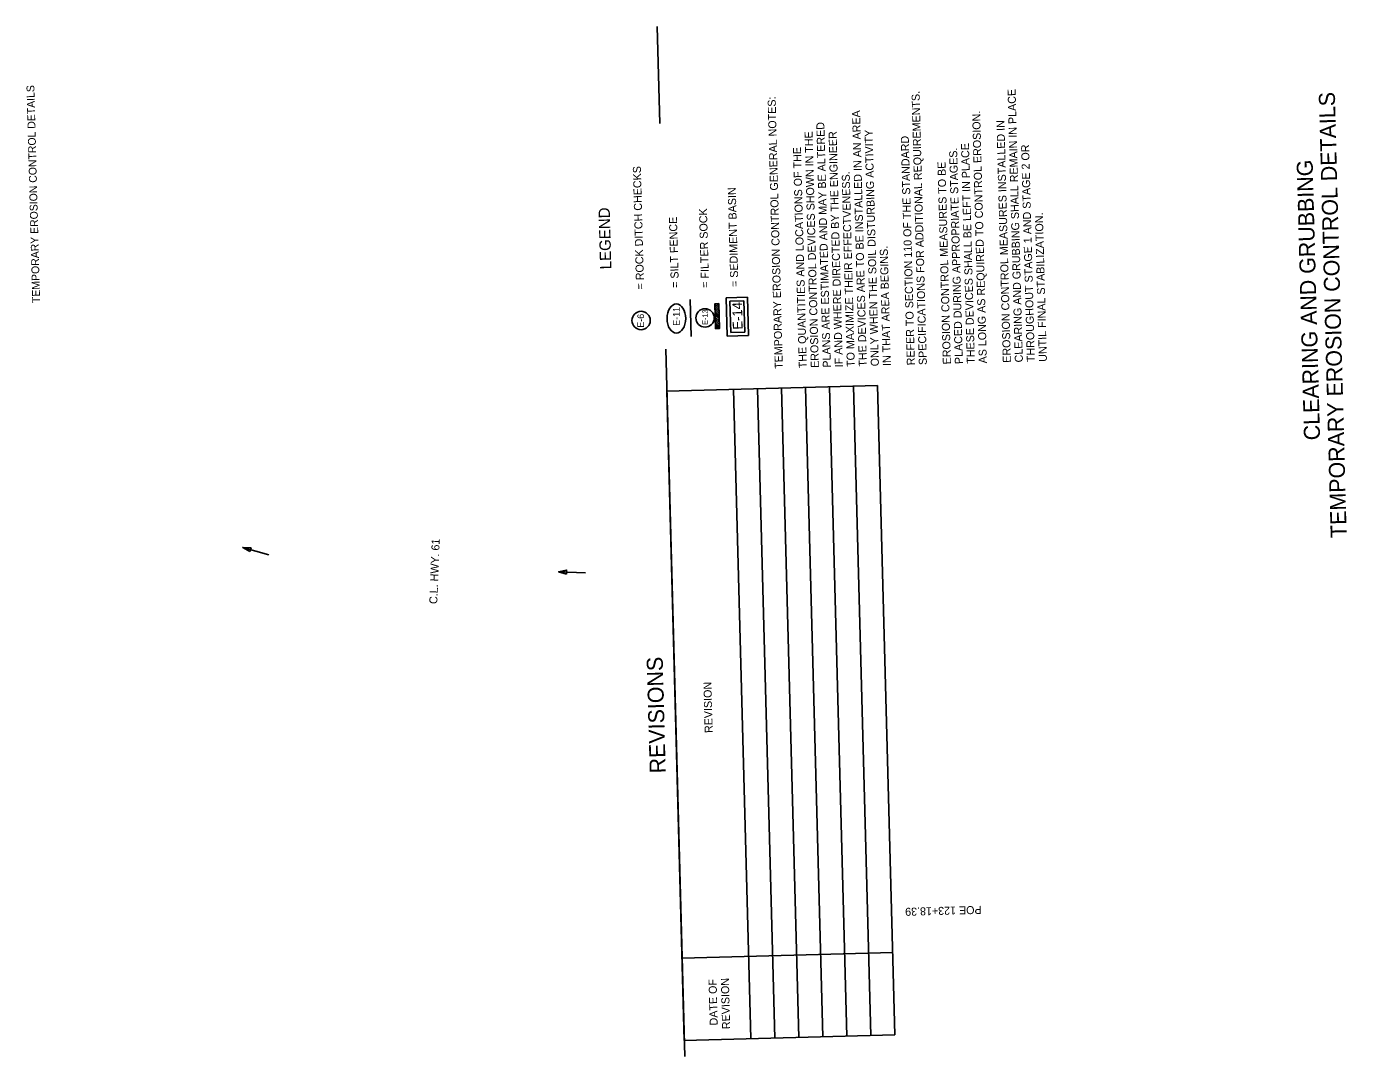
# Model space of a CAD drawing. Extents: x 1930579 to 1931598, y 596452 to 598587.
# Drawn here: x 1930608 to 1931598, y 597815 to 598587 of the extents above; entities that cross this region are included whole.
import ezdxf

# ---------------------------------------------------------------- set-up
doc = ezdxf.new("R2010")
doc.units = 0
for name, color, linetype in [('R_Erosion', 7, 'Continuous'), ('S_CAL_CORNER', 7, 'Continuous'), ('S_IRON_PIN', 7, 'Continuous'), ('S_SECTION', 7, 'Continuous'), ('S_TITLE_BLOCK', 7, 'Continuous')]:
    doc.layers.add(name, color=color, linetype=linetype)

msp = doc.modelspace()

# ---------------------------------------------------------------- linework, layer by layer
at = {"layer": 'R_Erosion'}
for p, q in [((1931132.43, 598383.77), (1931148.43, 598384.2)), ((1931149.2, 598355.37), (1931148.43, 598384.2)), ((1931126.91, 598376.39), (1931124.05, 598379.1)), ((1931126.94, 598374.97), (1931124.08, 598377.68)), ((1931126.98, 598373.56), (1931124.12, 598376.27)), ((1931127.02, 598372.15), (1931124.16, 598374.86)), ((1931126.87, 598377.8), (1931125.27, 598379.32)), ((1931126.83, 598379.22), (1931126.68, 598379.36)), ((1931133.21, 598354.94), (1931132.43, 598383.77)), ((1931135.21, 598381.15), (1931145.8, 598381.43)), ((1931135.84, 598357.71), (1931135.21, 598381.15)), ((1931146.43, 598358), (1931145.8, 598381.43)), ((1931127.06, 598370.73), (1931124.2, 598373.44)), ((1931127.1, 598369.32), (1931124.24, 598372.03)), ((1931127.13, 598367.91), (1931124.27, 598370.62)), ((1931127.17, 598366.49), (1931124.31, 598369.2)), ((1931127.21, 598365.08), (1931124.35, 598367.79)), ((1931127.25, 598363.66), (1931124.39, 598366.37)), ((1931127.29, 598362.25), (1931124.43, 598364.96)), ((1931127.32, 598360.84), (1931124.46, 598363.55)), ((1931126.13, 598360.59), (1931124.5, 598362.13)), ((1931124.71, 598360.55), (1931124.54, 598360.72)), ((1931133.21, 598354.94), (1931149.2, 598355.37)), ((1931135.84, 598357.71), (1931146.43, 598358))]:
    msp.add_line(p, q, dxfattribs=at)
msp.add_lwpolyline([(1931106.13, 598354.71), (1931105.38, 598382.51)], dxfattribs=at)
msp.add_lwpolyline([(1931124.54, 598360.55), (1931124.04, 598379.28), (1931126.83, 598379.36), (1931127.33, 598360.62)], close=True, dxfattribs=at)
for centre in [(1931116.62, 598368.63), (1931068.69, 598366.69)]:
    msp.add_circle(centre, 6.88, dxfattribs=at)
msp.add_ellipse((1931095.11, 598368.17), major_axis=(0, 10.96), ratio=0.638788, dxfattribs=at)
at = {"layer": 'S_CAL_CORNER'}
for p, q in [((1931082.6, 598514.3), (1931080.64, 598587.13)), ((1931101.37, 597814.95), (1931087.13, 598345.31))]:
    msp.add_line(p, q, dxfattribs=at)
at = {"layer": 'S_IRON_PIN'}
for p, q in [((1930770.05, 598196.55), (1930789.55, 598191.07)), ((1931006.81, 598178.3), (1931027.05, 598177.54))]:
    msp.add_line(p, q, dxfattribs=at)
for points in [[(1930775.42, 598193.48), (1930770.05, 598196.55), (1930776.23, 598196.37)], [(1931012.75, 598176.58), (1931006.81, 598178.3), (1931012.86, 598179.57)]]:
    msp.add_lwpolyline(points, close=True, dxfattribs=at)
at = {"layer": 'S_TITLE_BLOCK'}
for p, q in [((1931087.98, 598313.68), (1931245.92, 598317.92)), ((1931151.03, 597828.39), (1931137.96, 598315.03)), ((1931169.02, 597828.88), (1931155.96, 598315.51)), ((1931187.01, 597829.36), (1931173.95, 598315.99)), ((1931205.01, 597829.84), (1931191.94, 598316.48)), ((1931223, 597830.33), (1931209.94, 598316.96)), ((1931241, 597830.81), (1931227.93, 598317.44)), ((1931258.99, 597831.29), (1931245.92, 598317.92)), ((1931101.05, 597827.05), (1931087.98, 598313.68)), ((1931099.39, 597888.84), (1931257.33, 597893.08)), ((1931101.05, 597827.05), (1931258.99, 597831.29))]:
    msp.add_line(p, q, dxfattribs=at)

# ---------------------------------------------------------------- texts
at = {"layer": 'R_Erosion'}
for s, height, rotation, p in [('= ROCK DITCH CHECKS', 6, 91.53769, (1931070.94, 598390.01)), ('= SEDIMENT BASIN', 6, 91.53769, (1931141.6, 598391.91)), ('LEGEND', 8.439, 91.53769, (1931046.38, 598405.14)), ('= SILT FENCE', 6, 91.53769, (1931096.97, 598391.24)), ('= FILTER SOCK', 6, 91.53769, (1931119.65, 598391.32)), ('E-11', 5, 90, (1931097.57, 598362.75)), ('E-13', 4, 90, (1931118.62, 598363.36)), ('E-14', 7.303, 91.53628, (1931144.8, 598359.97)), ('E-6 ', 5, 90, (1931070.86, 598361.27))]:
    msp.add_text(s, height=height, rotation=rotation, dxfattribs=at).set_placement(p)
at = {"layer": 'S_CAL_CORNER'}
msp.add_text('TEMPORARY EROSION CONTROL DETAILS', height=5.862, rotation=91.53769, dxfattribs=at).set_placement((1930618.12, 598379.88))
at = {"layer": 'S_IRON_PIN'}
for s, height, rotation, p in [('TEMPORARY EROSION CONTROL GENERAL NOTES:', 6, 91.53769, (1931174.95, 598330.5)), ('SPECIFICATIONS FOR ADDITIONAL REQUIREMENTS.', 6, 91.53769, (1931282.91, 598333.4)), ('CLEARING AND GRUBBING SHALL REMAIN IN PLACE ', 6, 91.53769, (1931354.89, 598335.33)), ('TEMPORARY EROSION CONTROL DETAILS', 12, 91.53769, (1931597.68, 598203.88)), ('THE DEVICES ARE TO BE INSTALLED IN AN AREA ', 6, 91.53769, (1931237.93, 598332.19)), ('AS LONG AS REQUIRED TO CONTROL EROSION.', 6, 91.53769, (1931327.9, 598334.6)), ('PLANS ARE ESTIMATED AND MAY BE ALTERED ', 6, 91.53769, (1931210.94, 598331.46)), ('EROSION CONTROL MEASURES INSTALLED IN', 6, 91.53769, (1931345.89, 598335.09)), ('EROSION CONTROL DEVICES SHOWN IN THE ', 6, 91.53769, (1931201.94, 598331.22)), ('IF AND WHERE DIRECTED BY THE ENGINEER ', 6, 91.53769, (1931219.94, 598331.71)), ('ONLY WHEN THE SOIL DISTURBING ACTIVITY', 6, 91.53769, (1931246.93, 598332.43)), ('REFER TO SECTION 110 OF THE STANDARD ', 6, 91.53769, (1931273.92, 598333.16)), ('THE QUANTITIES AND LOCATIONS OF THE', 6, 91.53769, (1931192.95, 598330.98)), ('PLACED DURING APPROPRIATE STAGES. ', 6, 91.53769, (1931309.9, 598334.12)), ('THESE DEVICES SHALL BE LEFT IN PLACE ', 6, 91.53769, (1931318.9, 598334.36)), ('THROUGHOUT STAGE 1 AND STAGE 2 OR ', 6, 91.53769, (1931363.89, 598335.57)), ('EROSION CONTROL MEASURES TO BE', 6, 91.53769, (1931300.91, 598333.88)), ('CLEARING AND GRUBBING', 12, 91.53769, (1931577.71, 598277.05)), ('TO MAXIMIZE THEIR EFFECTVENESS. ', 6, 91.53769, (1931228.93, 598331.95)), ('UNTIL FINAL STABILIZATION.', 6, 91.53769, (1931372.88, 598335.81)), ('IN THAT AREA BEGINS.', 6, 91.53769, (1931255.92, 598332.67)), ('C.L. HWY. 61', 6, 87.79623, (1930915.84, 598154.09))]:
    msp.add_text(s, height=height, rotation=rotation, dxfattribs=at).set_placement(p)
at = {"layer": 'S_SECTION'}
msp.add_text('POE 123+18.39', height=6, rotation=181.53769, dxfattribs=at).set_placement((1931323.86, 597927.97))
at = {"layer": 'S_TITLE_BLOCK'}
for s, height, p in [('REVISIONS', 12, (1931087.16, 598027.41)), ('REVISION', 6, (1931122.37, 598057.57)), ('DATE OF', 6, (1931126.13, 597838.37)), ('REVISION', 6, (1931135.45, 597835.62))]:
    msp.add_text(s, height=height, rotation=91.53769, dxfattribs=at).set_placement(p)

doc.saveas('drawing.dxf')
